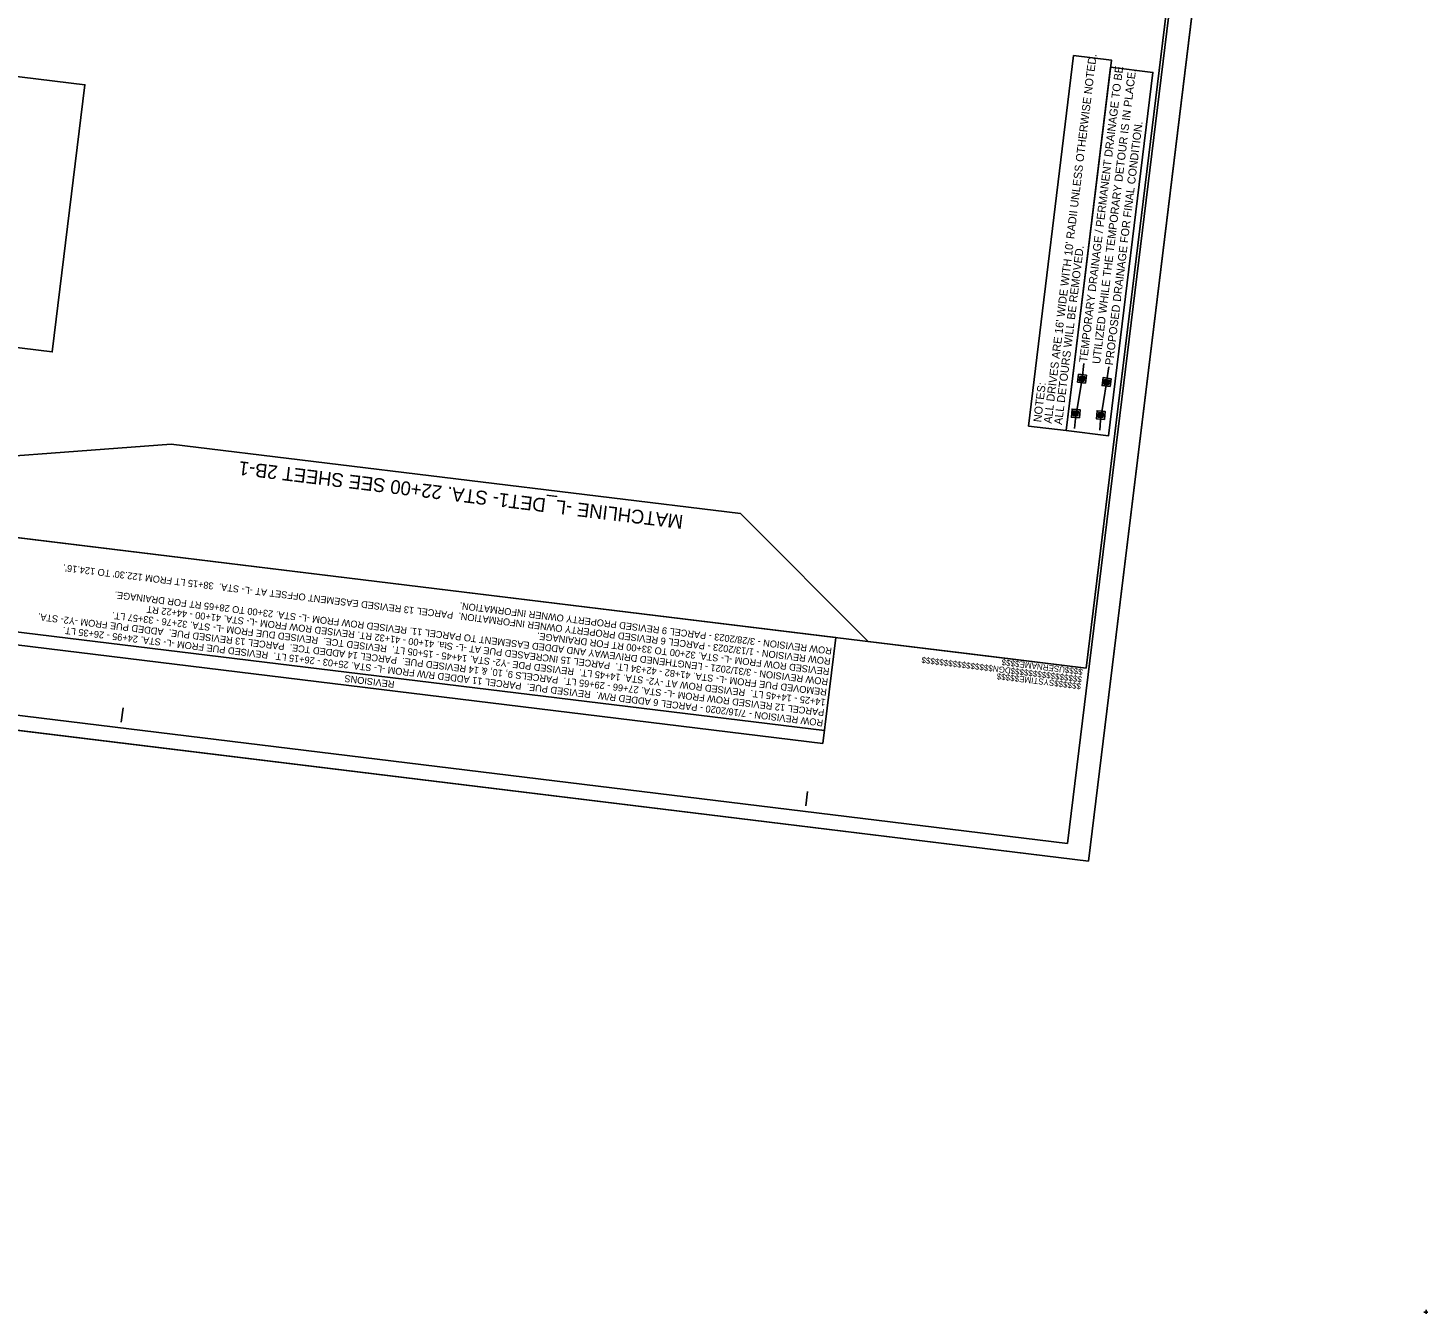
# Model space of a CAD drawing. Extents: x 480344 to 482186, y 489602 to 491961.
# Drawn here: x 480967 to 482186, y 489763 to 490882 of the extents above; entities that cross this region are included whole.
import ezdxf

# ---------------------------------------------------------------- set-up
doc = ezdxf.new("R2010")
doc.units = 0
for name, color, linetype in [('Matchline', 7, 'Continuous'), ('Matchline Text', 7, 'Continuous'), ('Old_Level_1', 7, 'Continuous'), ('Old_Level_41', 7, 'Continuous'), ('Prop Drainage Structure CELL', 7, 'Continuous'), ('Prop DSN Text', 7, 'Continuous'), ('Prop Grid Mask', 7, 'Continuous'), ('Sheet Block Revision CELL', 7, 'Continuous'), ('Sheet Clip Boundary CELL', 7, 'Continuous'), ('Sheet Cutting Line CELL', 7, 'Continuous'), ('Sheet Data Field CELL', 7, 'Continuous'), ('Sheet Layout Plan Border', 7, 'Continuous'), ('Sheet Plan CELL', 7, 'Continuous'), ('Sheet Plot Border Inside CELL', 7, 'Continuous'), ('Sheet Plot Border Outside CELL', 7, 'Continuous')]:
    doc.layers.add(name, color=color, linetype=linetype)

msp = doc.modelspace()

# ---------------------------------------------------------------- linework, layer by layer
at = {"layer": 'Matchline'}
msp.add_line((481587.5, 490459.2), (481091.9, 490519.7), dxfattribs=at)
at = {"layer": 'Old_Level_1'}
for p, q in [((482185.5, 489764.5), (482182, 489764.5)), ((482183.8, 489766.3), (482183.8, 489762.8))]:
    msp.add_line(p, q, dxfattribs=at)
at = {"layer": 'Old_Level_41'}
for p, q in [((481905.9, 490573.6), (481907.7, 490586.9)), ((481900.6, 490540.4), (481905.8, 490573.1)), ((481903.9, 490573.9), (481903.9, 490573.9)), ((481905.7, 490572.5), (481905.7, 490572.5)), ((481905.9, 490573.6), (481905.9, 490573.6)), ((481906, 490574.8), (481906, 490574.8)), ((481907.9, 490573.4), (481907.9, 490573.4)), ((481898.9, 490545.1), (481898.9, 490545.1)), ((481900, 490531.9), (481900.6, 490540.4)), ((481900.8, 490543.8), (481900.8, 490543.8)), ((481900.9, 490544.9), (481900.9, 490544.9)), ((481901, 490546.1), (481901, 490546.1)), ((481902.9, 490544.8), (481902.9, 490544.8))]:
    msp.add_line(p, q, dxfattribs=at)
for points in [[(481908.9, 490569.7), (481902, 490570.6), (481902.9, 490577.5), (481909.8, 490576.6)], [(481907.6, 490571.4), (481903.6, 490571.9), (481904.2, 490575.9), (481908.1, 490575.3)], [(481904.1, 490541.2), (481897.1, 490541.7), (481897.6, 490548.7), (481904.6, 490548.2)], [(481902.7, 490542.8), (481898.7, 490543.1), (481899, 490547.1), (481903, 490546.8)]]:
    msp.add_lwpolyline(points, close=True, dxfattribs=at)
for points in [[(481907.7, 490572.3), (481903.8, 490572.8), (481904.1, 490575), (481908, 490574.5), (481907.7, 490572.3)], [(481905.7, 490572.5), (481903.8, 490572.8), (481904.1, 490575), (481906, 490574.7), (481905.7, 490572.5)], [(481907.7, 490572.2), (481903.8, 490572.7), (481904.1, 490575), (481908, 490574.5), (481907.7, 490572.2)], [(481904.8, 490573.1), (481904, 490573.2), (481903.9, 490573), (481904.8, 490572.9), (481904.8, 490573.1)], [(481904.9, 490573.6), (481904, 490573.7), (481904.1, 490574), (481904.9, 490573.9), (481904.9, 490573.6)], [(481904.8, 490573.2), (481904, 490573.3), (481904, 490573.6), (481904.9, 490573.5), (481904.8, 490573.2)], [(481905, 490574.4), (481904.1, 490574.5), (481904.2, 490574.8), (481905, 490574.7), (481905, 490574.4)], [(481904.9, 490574), (481904.1, 490574.1), (481904.1, 490574.4), (481905, 490574.3), (481904.9, 490574)], [(481905.7, 490573.1), (481904.9, 490573.2), (481904.9, 490573.5), (481905.8, 490573.4), (481905.7, 490573.1)], [(481905.7, 490573), (481904.9, 490573.1), (481904.9, 490572.8), (481905.7, 490572.7), (481905.7, 490573)], [(481905.8, 490573.9), (481905, 490574), (481905, 490574.3), (481905.9, 490574.1), (481905.8, 490573.9)], [(481905.8, 490573.5), (481905, 490573.6), (481905, 490573.9), (481905.8, 490573.8), (481905.8, 490573.5)], [(481905.9, 490574.3), (481905.1, 490574.4), (481905.1, 490574.6), (481905.9, 490574.5), (481905.9, 490574.3)], [(481907.7, 490572.3), (481905.8, 490572.5), (481906, 490574.7), (481907.9, 490574.5), (481907.7, 490572.3)], [(481906.7, 490573), (481905.9, 490573.1), (481906, 490573.4), (481906.8, 490573.3), (481906.7, 490573)], [(481906.7, 490572.6), (481905.9, 490572.7), (481905.9, 490573), (481906.7, 490572.9), (481906.7, 490572.6)], [(481906.8, 490573.7), (481906, 490573.9), (481906.1, 490574.1), (481906.9, 490574), (481906.8, 490573.7)], [(481906.8, 490573.4), (481906, 490573.5), (481906, 490573.7), (481906.8, 490573.6), (481906.8, 490573.4)], [(481906.9, 490574.1), (481906.1, 490574.2), (481906.1, 490574.5), (481906.9, 490574.4), (481906.9, 490574.1)], [(481907.7, 490572.9), (481906.8, 490573), (481906.9, 490573.2), (481907.7, 490573.1), (481907.7, 490572.9)], [(481907.6, 490572.5), (481906.8, 490572.6), (481906.8, 490572.9), (481907.6, 490572.7), (481907.6, 490572.5)], [(481907.8, 490573.6), (481906.9, 490573.7), (481907, 490574), (481907.8, 490573.9), (481907.8, 490573.6)], [(481907.7, 490573.2), (481906.9, 490573.4), (481906.9, 490573.6), (481907.7, 490573.5), (481907.7, 490573.2)], [(481907.8, 490574), (481907, 490574.1), (481907, 490574.4), (481907.8, 490574.3), (481907.8, 490574)], [(481902.8, 490543.6), (481898.8, 490543.9), (481899, 490546.2), (481903, 490545.9), (481902.8, 490543.6)], [(481902.7, 490543.7), (481898.9, 490544), (481899, 490546.2), (481902.9, 490545.9), (481902.7, 490543.7)], [(481900.8, 490543.8), (481898.9, 490544), (481899, 490546.1), (481900.9, 490546), (481900.8, 490543.8)], [(481899.9, 490544.9), (481899, 490544.9), (481899, 490545.2), (481899.9, 490545.1), (481899.9, 490544.9)], [(481899.8, 490544.5), (481899, 490544.5), (481899, 490544.8), (481899.8, 490544.7), (481899.8, 490544.5)], [(481899.8, 490544.4), (481899, 490544.4), (481899, 490544.1), (481899.8, 490544.1), (481899.8, 490544.4)], [(481899.9, 490545.6), (481899.1, 490545.7), (481899.1, 490546), (481899.9, 490545.9), (481899.9, 490545.6)], [(481899.9, 490545.2), (481899.1, 490545.3), (481899.1, 490545.6), (481899.9, 490545.5), (481899.9, 490545.2)], [(481900.8, 490544.8), (481899.9, 490544.9), (481900, 490545.1), (481900.8, 490545.1), (481900.8, 490544.8)], [(481900.7, 490544.4), (481899.9, 490544.5), (481899.9, 490544.7), (481900.8, 490544.7), (481900.7, 490544.4)], [(481900.7, 490544.3), (481899.9, 490544.4), (481899.9, 490544.1), (481900.7, 490544), (481900.7, 490544.3)], [(481900.8, 490545.6), (481900, 490545.6), (481900, 490545.9), (481900.8, 490545.8), (481900.8, 490545.6)], [(481900.8, 490545.2), (481900, 490545.2), (481900, 490545.5), (481900.8, 490545.4), (481900.8, 490545.2)], [(481902.7, 490543.7), (481900.8, 490543.8), (481901, 490546), (481902.9, 490545.9), (481902.7, 490543.7)], [(481901.8, 490544.3), (481900.9, 490544.4), (481900.9, 490544.7), (481901.8, 490544.6), (481901.8, 490544.3)], [(481901.7, 490544), (481900.9, 490544), (481900.9, 490544.3), (481901.8, 490544.2), (481901.7, 490544)], [(481901.8, 490545.5), (481901, 490545.5), (481901, 490545.8), (481901.9, 490545.8), (481901.8, 490545.5)], [(481901.8, 490545.1), (481901, 490545.2), (481901, 490545.4), (481901.8, 490545.4), (481901.8, 490545.1)], [(481901.8, 490544.7), (481901, 490544.8), (481901, 490545), (481901.8, 490545), (481901.8, 490544.7)], [(481902.7, 490544.3), (481901.8, 490544.3), (481901.9, 490544.6), (481902.7, 490544.5), (481902.7, 490544.3)], [(481902.6, 490543.9), (481901.8, 490543.9), (481901.8, 490544.2), (481902.7, 490544.2), (481902.6, 490543.9)], [(481902.8, 490545.4), (481901.9, 490545.5), (481901.9, 490545.8), (481902.8, 490545.7), (481902.8, 490545.4)], [(481902.7, 490545), (481901.9, 490545.1), (481901.9, 490545.4), (481902.7, 490545.3), (481902.7, 490545)], [(481902.7, 490544.7), (481901.9, 490544.7), (481901.9, 490545), (481902.7, 490544.9), (481902.7, 490544.7)]]:
    msp.add_lwpolyline(points, dxfattribs=at)
at = {"layer": 'Prop Drainage Structure CELL'}
for p, q in [((481884.5, 490576.6), (481886.2, 490589.9)), ((481878.7, 490541.9), (481884.5, 490576.4)), ((481882.5, 490576.8), (481882.5, 490576.8)), ((481884.5, 490576.6), (481884.5, 490576.6)), ((481884.6, 490577.7), (481884.6, 490577.7)), ((481886.5, 490576.3), (481886.5, 490576.3)), ((481884.3, 490575.4), (481884.3, 490575.4)), ((481877.1, 490546.5), (481877.1, 490546.5)), ((481878.1, 490533.4), (481878.7, 490541.9)), ((481879, 490545.2), (481879, 490545.2)), ((481879.1, 490547.5), (481879.1, 490547.5)), ((481879.1, 490546.4), (481879.1, 490546.4)), ((481881.1, 490546.2), (481881.1, 490546.2))]:
    msp.add_line(p, q, dxfattribs=at)
for points in [[(481887.5, 490572.6), (481880.6, 490573.6), (481881.5, 490580.5), (481888.4, 490579.6)], [(481886.2, 490574.3), (481882.2, 490574.8), (481882.8, 490578.8), (481886.7, 490578.3)], [(481882.3, 490542.6), (481875.3, 490543.1), (481875.8, 490550.1), (481882.8, 490549.6)], [(481880.9, 490544.2), (481876.9, 490544.5), (481877.2, 490548.5), (481881.2, 490548.2)]]:
    msp.add_lwpolyline(points, close=True, dxfattribs=at)
for points in [[(481886.3, 490575.1), (481882.3, 490575.7), (481882.6, 490578), (481886.6, 490577.5), (481886.3, 490575.1)], [(481886.3, 490575.2), (481882.4, 490575.7), (481882.7, 490577.9), (481886.5, 490577.4), (481886.3, 490575.2)], [(481884.3, 490575.5), (481882.4, 490575.7), (481882.7, 490577.9), (481884.6, 490577.7), (481884.3, 490575.5)], [(481883.4, 490576.1), (481882.6, 490576.2), (481882.5, 490575.9), (481883.4, 490575.8), (481883.4, 490576.1)], [(481883.5, 490576.6), (481882.6, 490576.7), (481882.7, 490576.9), (481883.5, 490576.8), (481883.5, 490576.6)], [(481883.4, 490576.2), (481882.6, 490576.3), (481882.6, 490576.6), (481883.4, 490576.4), (481883.4, 490576.2)], [(481883.6, 490577.3), (481882.7, 490577.4), (481882.8, 490577.7), (481883.6, 490577.6), (481883.6, 490577.3)], [(481883.5, 490576.9), (481882.7, 490577.1), (481882.7, 490577.3), (481883.5, 490577.2), (481883.5, 490576.9)], [(481884.3, 490575.9), (481883.5, 490576.1), (481883.4, 490575.8), (481884.3, 490575.7), (481884.3, 490575.9)], [(481884.4, 490576.4), (481883.5, 490576.6), (481883.6, 490576.8), (481884.4, 490576.7), (481884.4, 490576.4)], [(481884.3, 490576.1), (481883.5, 490576.2), (481883.5, 490576.4), (481884.4, 490576.3), (481884.3, 490576.1)], [(481884.5, 490577.2), (481883.6, 490577.3), (481883.7, 490577.6), (481884.5, 490577.5), (481884.5, 490577.2)], [(481884.4, 490576.8), (481883.6, 490576.9), (481883.6, 490577.2), (481884.5, 490577.1), (481884.4, 490576.8)], [(481886.2, 490575.2), (481884.3, 490575.5), (481884.6, 490577.6), (481886.5, 490577.4), (481886.2, 490575.2)], [(481885.3, 490575.9), (481884.5, 490576), (481884.5, 490576.3), (481885.4, 490576.2), (481885.3, 490575.9)], [(481885.4, 490576.7), (481884.6, 490576.8), (481884.6, 490577.1), (481885.5, 490577), (481885.4, 490576.7)], [(481885.4, 490576.3), (481884.6, 490576.4), (481884.6, 490576.7), (481885.4, 490576.6), (481885.4, 490576.3)], [(481885.5, 490577.1), (481884.7, 490577.2), (481884.7, 490577.5), (481885.5, 490577.3), (481885.5, 490577.1)], [(481886.2, 490575.8), (481885.4, 490575.9), (481885.4, 490576.2), (481886.3, 490576.1), (481886.2, 490575.8)], [(481886.3, 490576.6), (481885.5, 490576.7), (481885.5, 490576.9), (481886.4, 490576.8), (481886.3, 490576.6)], [(481886.3, 490576.2), (481885.5, 490576.3), (481885.5, 490576.6), (481886.3, 490576.5), (481886.3, 490576.2)], [(481886.4, 490577), (481885.6, 490577.1), (481885.6, 490577.3), (481886.4, 490577.2), (481886.4, 490577)], [(481885.3, 490575.5), (481884.5, 490575.7), (481884.5, 490575.9), (481885.3, 490575.8), (481885.3, 490575.5)], [(481886.2, 490575.4), (481885.4, 490575.5), (481885.4, 490575.8), (481886.2, 490575.7), (481886.2, 490575.4)], [(481881, 490545.1), (481877, 490545.4), (481877.1, 490547.7), (481881.1, 490547.4), (481881, 490545.1)], [(481880.9, 490545.1), (481877.1, 490545.4), (481877.2, 490547.6), (481881.1, 490547.3), (481880.9, 490545.1)], [(481879, 490545.3), (481877.1, 490545.4), (481877.2, 490547.6), (481879.1, 490547.5), (481879, 490545.3)], [(481878.1, 490546.7), (481877.2, 490546.8), (481877.3, 490547), (481878.1, 490547), (481878.1, 490546.7)], [(481878, 490546.3), (481877.2, 490546.4), (481877.2, 490546.6), (481878.1, 490546.6), (481878, 490546.3)], [(481878, 490545.9), (481877.2, 490546), (481877.2, 490546.3), (481878, 490546.2), (481878, 490545.9)], [(481878, 490545.8), (481877.2, 490545.9), (481877.2, 490545.6), (481878, 490545.5), (481878, 490545.8)], [(481878.1, 490547.1), (481877.3, 490547.1), (481877.3, 490547.4), (481878.1, 490547.4), (481878.1, 490547.1)], [(481879, 490546.3), (481878.1, 490546.3), (481878.1, 490546.6), (481879, 490546.5), (481879, 490546.3)], [(481878.9, 490545.9), (481878.1, 490545.9), (481878.1, 490546.2), (481879, 490546.1), (481878.9, 490545.9)], [(481878.9, 490545.8), (481878.1, 490545.8), (481878.1, 490545.5), (481878.9, 490545.5), (481878.9, 490545.8)], [(481879, 490547), (481878.2, 490547.1), (481878.2, 490547.3), (481879, 490547.3), (481879, 490547)], [(481879, 490546.6), (481878.2, 490546.7), (481878.2, 490547), (481879, 490546.9), (481879, 490546.6)], [(481880.9, 490545.2), (481879, 490545.3), (481879.1, 490547.5), (481881.1, 490547.3), (481880.9, 490545.2)], [(481880, 490546.2), (481879.1, 490546.2), (481879.2, 490546.5), (481880, 490546.5), (481880, 490546.2)], [(481879.9, 490545.8), (481879.1, 490545.9), (481879.1, 490546.1), (481880, 490546.1), (481879.9, 490545.8)], [(481879.9, 490545.4), (481879.1, 490545.5), (481879.1, 490545.7), (481879.9, 490545.7), (481879.9, 490545.4)], [(481880, 490546.9), (481879.2, 490547), (481879.2, 490547.3), (481880.1, 490547.2), (481880, 490546.9)], [(481880, 490546.6), (481879.2, 490546.6), (481879.2, 490546.9), (481880, 490546.8), (481880, 490546.6)], [(481880.9, 490545.7), (481880, 490545.8), (481880.1, 490546.1), (481880.9, 490546), (481880.9, 490545.7)], [(481880.8, 490545.3), (481880, 490545.4), (481880, 490545.7), (481880.9, 490545.6), (481880.8, 490545.3)], [(481880.9, 490546.9), (481880.1, 490546.9), (481880.1, 490547.2), (481881, 490547.2), (481880.9, 490546.9)], [(481880.9, 490546.5), (481880.1, 490546.6), (481880.1, 490546.8), (481880.9, 490546.8), (481880.9, 490546.5)], [(481880.9, 490546.1), (481880.1, 490546.2), (481880.1, 490546.4), (481880.9, 490546.4), (481880.9, 490546.1)]]:
    msp.add_lwpolyline(points, dxfattribs=at)
at = {"layer": 'Prop Grid Mask'}
for points in [[(481837.8, 490535.4), (481877.2, 490857.8), (481910.1, 490853.8), (481870.8, 490531.4)], [(481870.8, 490531.4), (481909.4, 490847.6), (481946.2, 490843.1), (481907.6, 490526.9)]]:
    msp.add_lwpolyline(points, close=True, dxfattribs=at)
at = {"layer": 'Sheet Block Revision CELL'}
msp.add_line((481660.4, 490270.4), (480875.6, 490366.3), dxfattribs=at)
msp.add_lwpolyline([(481659, 490259.3), (480874.2, 490355.2), (480885.4, 490447.2), (481670.2, 490351.4)], close=True, dxfattribs=at)
at = {"layer": 'Sheet Clip Boundary CELL'}
msp.add_lwpolyline([(480879.2, 490613.3), (480907.6, 490845.7), (481017, 490832.4), (480988.6, 490599.9)], close=True, dxfattribs=at)
at = {"layer": 'Sheet Cutting Line CELL'}
for p, q in [((481890.2, 490156.8), (482094.3, 491827.9)), ((480803.3, 490289.5), (481890.2, 490156.8))]:
    msp.add_line(p, q, dxfattribs=at)
at = {"layer": 'Sheet Layout Plan Border'}
for points in [[(481091.9, 490519.7), (481587.5, 490459.2), (481698.3, 490347.9), (481789.2, 490336.8), (481888, 490324.8), (481894.1, 490374.4), (482045.3, 491612.4), (481950.4, 491623.3), (481975.4, 491825.3), (481441.9, 491890.4), (481190.7, 491844.8), (481175.6, 491721.4), (481003.4, 491742.5), (480851.8, 490501.7)], [(481091.9, 490519.7), (481587.5, 490459.2), (481698.3, 490347.9), (481789.2, 490336.8), (481888, 490324.8), (481894.1, 490374.4), (482045.3, 491612.4), (481950.4, 491623.3), (481955.4, 491662), (481633.7, 491701.3), (481441.9, 491890.4), (481190.7, 491844.8), (481175.6, 491721.4), (481003.4, 491742.5), (480851.8, 490501.7)]]:
    msp.add_lwpolyline(points, close=True, dxfattribs=at)
at = {"layer": 'Sheet Plan CELL'}
for p, q in [((481888, 490324.8), (481888, 490324.8)), ((481048.6, 490277.7), (481050.1, 490290.1)), ((481644.2, 490205), (481645.7, 490217.4))]:
    msp.add_line(p, q, dxfattribs=at)
for points in [[(481027.6, 491941), (480845.8, 490452.1), (481888, 490324.8), (482069.9, 491813.7)], [(481888, 490324.8), (480845.8, 490452), (481003.4, 491742.4), (481152.3, 491724.3), (481176.6, 491922.8), (482069.9, 491813.7)]]:
    msp.add_lwpolyline(points, close=True, dxfattribs=at)
at = {"layer": 'Sheet Plot Border Inside CELL'}
msp.add_lwpolyline([(481871.9, 490172.1), (482073.9, 491825.8), (481026.7, 491953.7), (480824.7, 490300)], close=True, dxfattribs=at)
at = {"layer": 'Sheet Plot Border Outside CELL'}
msp.add_lwpolyline([(481890.2, 490156.8), (482094.3, 491827.9), (481007.4, 491960.6), (480803.3, 490289.5)], close=True, dxfattribs=at)

# ---------------------------------------------------------------- texts
at = {"layer": 'Matchline Text'}
msp.add_text('MATCHLINE -L_DET1- STA. 22+00 SEE SHEET 2B-1', height=12, rotation=173.0365, dxfattribs=at).set_placement((481538, 490457.7))
at = {"layer": 'Prop DSN Text'}
for s, p in [("ALL DRIVES ARE 16' WIDE WITH 10' RADII UNLESS OTHERWISE NOTED. ", (481858, 490537.3)), ('ALL DETOURS WILL BE REMOVED. ', (481867.1, 490536.2)), ('NOTES: ', (481848.9, 490538.4))]:
    msp.add_text(s, height=7, rotation=83.0365, dxfattribs=at).set_placement(p)
at = {"layer": 'Sheet Block Revision CELL'}
for s, p in [("ROW REVISION - 1/13/2023 - PARCEL 6 REVISED PROPERTY OWNER INFORMATION.  PARCEL 13 REVISED EASEMENT OFFSET AT -L- STA.  38+15 LT FROM 122.30' TO 124.16'.", (481666.1, 490333.5)), ('ROW REVISION - 3/31/2021 - LENGTHENED DRIVEWAY AND ADDED EASEMENT TO PARCEL 11. REVISED ROW FROM -L- STA. 23+00 TO 28+65 RT FOR DRAINAGE. ', (481663.9, 490315.7)), ('ROW REVISION - 3/28/2023 - PARCEL 9 REVISED PROPERTY OWNER INFORMATION. ', (481667.2, 490342.5)), ('PARCEL 12 REVISED ROW FROM -L- STA. 27+66 - 29+65 LT.  PARCELS 9, 10, & 14 REVISED PUE.  PARCEL 14 ADDED TCE.  PARCEL 13 REVISED PUE.  ADDED PUE FROM -Y2- STA.', (481660.6, 490288.9)), ('14+25 - 14+45 LT.  REVISED ROW AT -Y2- STA. 14+45 LT.  REVISED PDE -Y2- STA. 14+45 - 15+05 LT.  REVISED TCE.  REVISED DUE FROM -L- STA. 32+76 - 33+57 LT. ', (481661.7, 490297.8)), ('REMOVED PUE FROM -L- STA. 41+82 - 42+34 LT.  PARCEL 15 INCREASED PUE AT -L- Sta. 41+00 - 41+32 RT. REVISED ROW FROM -L- STA. 41+00 - 44+22 RT', (481662.8, 490306.7)), ('ROW REVISION - 7/16/2020 - PARCEL 6 ADDED R/W.  REVISED PUE.  PARCEL 11 ADDED R/W FROM -L- STA. 25+03 - 26+15 LT.  REVISED PUE FROM -L- STA. 24+95 - 26+35 LT. ', (481659.6, 490279.9)), ('REVISED ROW FROM -L- STA. 32+00 TO 33+00 RT FOR DRAINAGE.', (481665, 490324.6)), ('REVISIONS', (481286.6, 490313.5))]:
    msp.add_text(s, height=6, rotation=173.0365, dxfattribs=at).set_placement(p)
at = {"layer": 'Sheet Data Field CELL'}
for s, p in [('TEMPORARY DRAINAGE / PERMANENT DRAINAGE TO BE ', (481888.9, 490590.5)), ('UTILIZED WHILE THE TEMPORARY DETOUR IS IN PLACE.', (481900.2, 490589.1)), ('PROPOSED DRAINAGE FOR FINAL CONDITION.', (481911.4, 490588))]:
    msp.add_text(s, height=7, rotation=83.0365, dxfattribs=at).set_placement(p)
at = {"layer": 'Sheet Plan CELL'}
for s, p in [('$$$$$$$$$$$$$$$$DGN$$$$$$$$$$$$$$$$', (481884.8, 490317.5)), ('$$$$USERNAME$$$$', (481885.5, 490324)), ('$$$$$$SYSTIME$$$$$', (481884, 490311.4))]:
    msp.add_text(s, height=5.25, rotation=173.0365, dxfattribs=at).set_placement(p)

doc.saveas('drawing.dxf')
